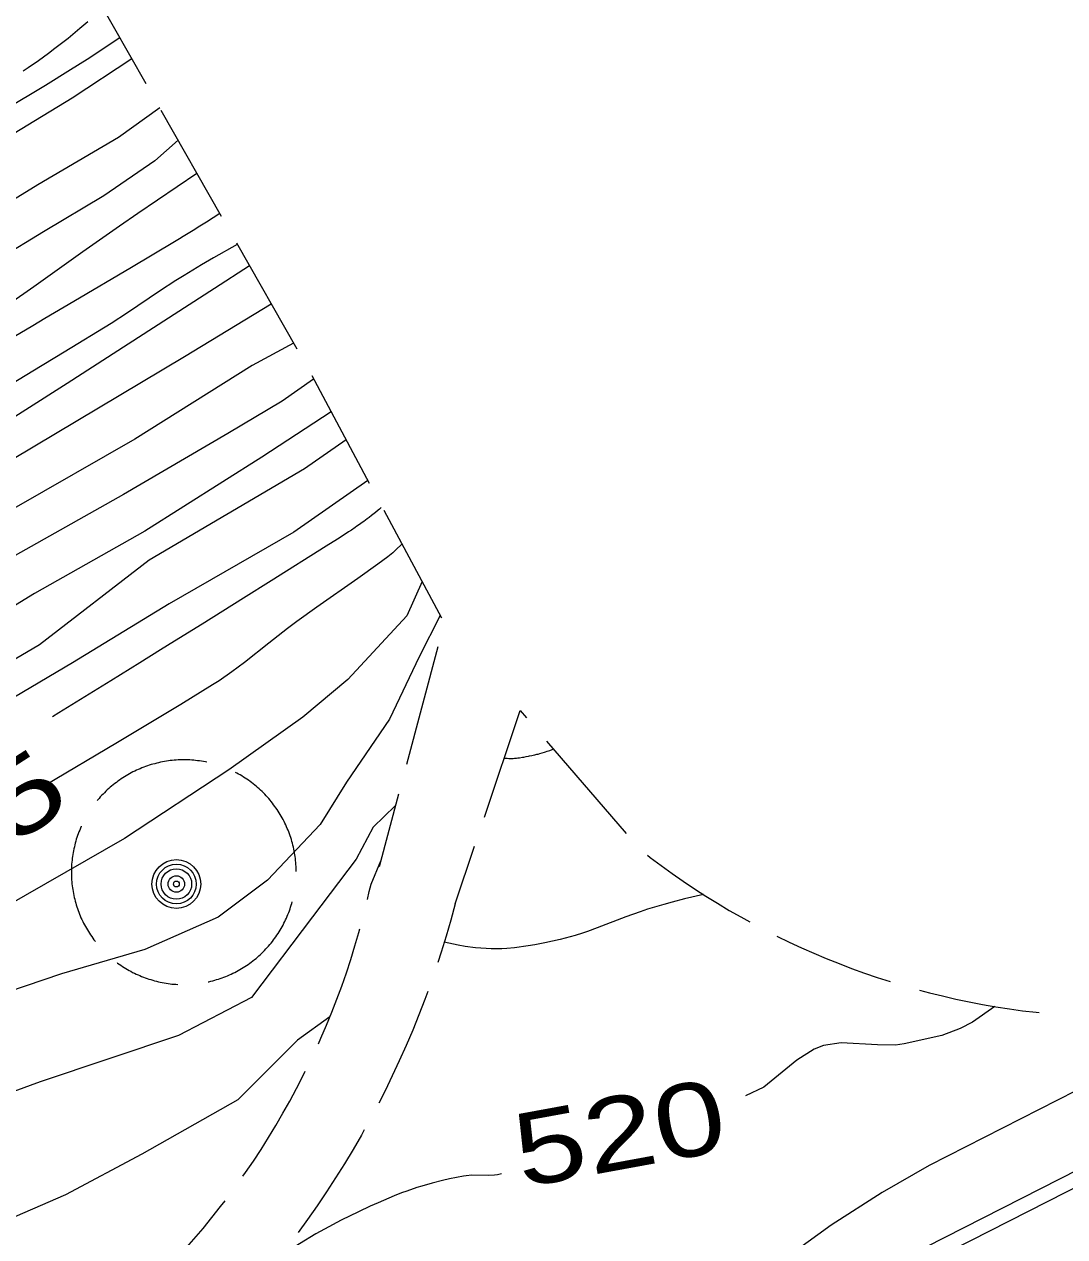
# Model space of a CAD drawing. Extents: x 2361284 to 2366480, y 6976556 to 6985346.
# Drawn here: x 2364307.7 to 2364375.8, y 6978882 to 6978961.5 of the extents above; entities that cross this region are included whole.
import ezdxf
from ezdxf.enums import TextEntityAlignment as Align

# ---------------------------------------------------------------- set-up
doc = ezdxf.new("R2010")
doc.units = 0
doc.header["$LTSCALE"] = 1.9
for name, color, linetype, lineweight in [('12', 7, 'Continuous', 13), ('13', 7, 'Continuous', 13), ('24', 7, 'Continuous', 13), ('25', 7, 'Continuous', 13), ('3', 7, 'Continuous', 13), ('4', 7, 'Continuous', 13), ('6', 7, 'Continuous', 13)]:
    doc.layers.add(name, color=color, linetype=linetype, lineweight=lineweight)

msp = doc.modelspace()

# ---------------------------------------------------------------- linework, layer by layer
at = {"layer": '12'}
for points in [[(2364313.918, 6978960.587), (2364311.774, 6978959.17), (2364310.694, 6978958.476), (2364309.057, 6978957.459), (2364306.384, 6978955.853), (2364305.042, 6978955.059), (2364303.021, 6978953.882), (2364294.02, 6978948.696), (2364288.58, 6978945.564), (2364287.657, 6978945.042), (2364285.795, 6978944.028), (2364283.917, 6978943.04), (2364281.406, 6978941.739), (2364280.152, 6978941.085), (2364272.767, 6978937.243), (2364272.057, 6978936.862), (2364270.648, 6978936.079), (2364267.845, 6978934.487), (2364266.431, 6978933.713)], [(2364320.468, 6978949.068), (2364319.595, 6978948.512), (2364319.158, 6978948.235), (2364318.719, 6978947.96), (2364318.5, 6978947.824), (2364318.059, 6978947.553), (2364317.838, 6978947.419), (2364317.505, 6978947.219), (2364314.675, 6978945.538), (2364310.9, 6978943.299), (2364309.013, 6978942.179), (2364308.221, 6978941.708), (2364306.637, 6978940.764), (2364304.526, 6978939.506), (2364303.47, 6978938.878), (2364302.412, 6978938.252), (2364301.883, 6978937.94), (2364301.746, 6978937.861), (2364301.654, 6978937.81), (2364301.469, 6978937.709), (2364301.282, 6978937.611), (2364300.908, 6978937.416), (2364300.722, 6978937.318), (2364300.629, 6978937.268)], [(2364326.611, 6978938.216), (2364324.545, 6978936.776), (2364320.995, 6978934.652), (2364314.153, 6978930.657), (2364305.499, 6978925.774), (2364295.295, 6978919.817), (2364285.121, 6978913.85), (2364278.029, 6978909.862), (2364269.164, 6978904.928), (2364259.758, 6978899.318), (2364253.637, 6978896.12)], [(2364332.404, 6978927.41), (2364332.007, 6978927.026), (2364331.802, 6978926.842), (2364331.482, 6978926.581), (2364330.827, 6978926.096), (2364329.502, 6978925.148), (2364326.834, 6978923.283), (2364325.512, 6978922.334), (2364324.898, 6978921.873), (2364323.689, 6978920.922), (2364322.081, 6978919.649), (2364321.261, 6978919.035), (2364320.421, 6978918.45), (2364319.991, 6978918.172), (2364317.923, 6978916.897), (2364313.757, 6978914.402), (2364308.994, 6978911.557)], [(2364371.245, 6978897.098), (2364369.778, 6978896.069), (2364368.969, 6978895.656), (2364367.766, 6978895.208), (2364365.307, 6978894.651), (2364364.728, 6978894.579), (2364363.549, 6978894.588), (2364361.18, 6978894.717), (2364360.028, 6978894.551), (2364359.401, 6978894.313), (2364358.265, 6978893.576), (2364356.118, 6978891.827), (2364354.909, 6978891.251)], [(2364338.927, 6978886.13), (2364338.657, 6978886.07), (2364338.474, 6978886.046), (2364338.104, 6978886.027), (2364336.981, 6978886.041), (2364336.611, 6978886.015), (2364336.428, 6978885.986), (2364335.516, 6978885.8), (2364335.063, 6978885.697), (2364334.386, 6978885.528), (2364333.714, 6978885.339), (2364333.38, 6978885.236), (2364332.715, 6978885.012), (2364332.384, 6978884.89), (2364331.89, 6978884.693), (2364330.843, 6978884.244), (2364330.327, 6978884.013), (2364329.561, 6978883.657), (2364328.429, 6978883.098), (2364327.318, 6978882.507), (2364326.77, 6978882.198), (2364325.687, 6978881.55), (2364325.152, 6978881.211), (2364324.358, 6978880.681)]]:
    msp.add_lwpolyline(points, dxfattribs=at)
at = {"layer": '13'}
for points in [[(2364311.814, 6978961.634), (2364311.31, 6978961.188), (2364310.528, 6978960.545), (2364309.671, 6978959.882), (2364309.238, 6978959.558), (2364308.582, 6978959.083), (2364307.916, 6978958.624), (2364307.579, 6978958.402)], [(2364314.701, 6978959.203), (2364310.805, 6978956.626), (2364301.568, 6978951.008), (2364293.845, 6978946.104), (2364290.559, 6978944.303), (2364286.069, 6978942.094), (2364283.864, 6978940.92), (2364280.716, 6978938.984), (2364276.567, 6978936.318), (2364274.427, 6978935.099), (2364269.182, 6978932.479)], [(2364316.532, 6978955.99), (2364313.83, 6978954.045), (2364308.549, 6978950.944), (2364301.013, 6978946.312), (2364290.002, 6978940.078), (2364279.118, 6978934.144), (2364270.162, 6978929.378), (2364260.616, 6978924.797), (2364250.162, 6978919.738), (2364238.779, 6978913.839), (2364222.473, 6978904.794), (2364208.884, 6978898.294), (2364198.941, 6978893.349), (2364192.8, 6978890.28), (2364187.441, 6978887.919), (2364182.588, 6978886.174)], [(2364317.732, 6978953.872), (2364316.215, 6978952.527), (2364312.866, 6978950.235), (2364308.919, 6978947.858), (2364303.172, 6978944.383), (2364296.111, 6978940.047), (2364293.196, 6978938.609), (2364289.982, 6978936.897), (2364285.307, 6978934.273), (2364277.615, 6978930.199), (2364274.488, 6978928.779), (2364265.759, 6978924.536), (2364257, 6978920.083), (2364251.317, 6978917.199), (2364241.61, 6978912.586), (2364232.239, 6978907.367), (2364220.519, 6978902.065), (2364210.333, 6978897.408), (2364201.691, 6978893.355), (2364192.004, 6978887.792), (2364184.189, 6978883.929)], [(2364318.973, 6978951.693), (2364315.107, 6978949.077), (2364313.895, 6978948.243), (2364311.49, 6978946.548), (2364308.294, 6978944.271), (2364306.687, 6978943.145), (2364305.067, 6978942.038), (2364304.249, 6978941.494), (2364303.9, 6978941.269), (2364303.19, 6978940.839), (2364302.469, 6978940.428), (2364301.006, 6978939.643)], [(2364321.617, 6978947.048), (2364320.051, 6978946.169), (2364319.276, 6978945.716), (2364318.126, 6978945.015), (2364317.59, 6978944.673), (2364316.529, 6978943.971), (2364314.418, 6978942.553), (2364313.346, 6978941.87), (2364310.274, 6978939.986), (2364308.222, 6978938.736), (2364304.109, 6978936.251), (2364303.085, 6978935.642)], [(2364322.411, 6978945.636), (2364320.125, 6978944.144), (2364310.463, 6978937.922), (2364299.847, 6978931.181), (2364286.905, 6978923.987), (2364274.065, 6978916.445), (2364261.964, 6978910.31), (2364246.754, 6978902.725), (2364228.872, 6978893.373), (2364216.324, 6978887.844), (2364203.202, 6978880.669), (2364189.183, 6978874.156), (2364178.057, 6978868.389)], [(2364323.844, 6978943.13), (2364318.147, 6978939.686), (2364306.88, 6978932.948), (2364295.455, 6978926.009), (2364285.901, 6978920.148), (2364275.256, 6978914.176), (2364260.532, 6978906.236), (2364244.509, 6978897.973), (2364228.357, 6978890.738), (2364215.431, 6978883.976), (2364202.153, 6978876.299), (2364186.212, 6978868.926), (2364172.253, 6978862.503)], [(2364325.299, 6978940.564), (2364322.583, 6978939.118), (2364314.908, 6978934.274), (2364306.971, 6978929.738), (2364298.615, 6978924.909), (2364288.728, 6978919.404), (2364276.576, 6978912.129), (2364273.468, 6978910.461), (2364267.173, 6978907.279), (2364262.694, 6978905.157), (2364256.711, 6978902.354), (2364253.782, 6978900.831)], [(2364327.762, 6978936.066), (2364323.23, 6978933.103), (2364315.565, 6978928.26), (2364308.324, 6978924.161), (2364302.02, 6978920.301), (2364294.83, 6978916.112), (2364284.978, 6978909.978), (2364276.55, 6978905.398), (2364266.147, 6978899.499), (2364262.975, 6978897.89), (2364258.686, 6978895.86), (2364256.561, 6978894.807)], [(2364328.739, 6978934.245), (2364326.017, 6978932.33), (2364315.843, 6978926.363), (2364308.656, 6978920.804), (2364301.884, 6978916.819), (2364294.629, 6978912.04), (2364283.168, 6978905.721), (2364273.673, 6978900.83), (2364259.772, 6978893.627), (2364245.846, 6978886.685), (2364235.63, 6978882.178), (2364223.418, 6978875.931), (2364208.701, 6978868.14), (2364196.682, 6978861.656), (2364185.969, 6978857.625), (2364177.208, 6978853.631)], [(2364330.174, 6978931.579), (2364325.317, 6978928.183), (2364317.151, 6978923.485), (2364310.817, 6978919.634), (2364299.4, 6978912.866), (2364289.25, 6978906.569), (2364276.268, 6978899.285), (2364261.484, 6978891.283), (2364243.048, 6978882.278), (2364226.448, 6978874.88), (2364207.744, 6978865.701), (2364193.385, 6978858.155), (2364173.139, 6978849.311)], [(2364331.051, 6978929.797), (2364330.927, 6978929.69), (2364330.843, 6978929.62), (2364330.675, 6978929.481), (2364330.59, 6978929.412), (2364330.418, 6978929.277), (2364330.245, 6978929.145), (2364330.129, 6978929.057), (2364329.895, 6978928.886), (2364329.807, 6978928.822), (2364329.629, 6978928.696), (2364329.45, 6978928.572), (2364329.33, 6978928.49), (2364329.088, 6978928.328), (2364328.906, 6978928.208), (2364328.541, 6978927.971), (2364328.173, 6978927.737), (2364327.435, 6978927.273), (2364323.824, 6978925.002), (2364322.018, 6978923.867), (2364319.308, 6978922.167), (2364317.5, 6978921.036), (2364316.595, 6978920.471), (2364315.237, 6978919.626), (2364314.601, 6978919.231), (2364313.328, 6978918.445), (2364311.63, 6978917.397), (2364310.782, 6978916.872), (2364309.934, 6978916.346), (2364309.511, 6978916.082)], [(2364333.718, 6978924.952), (2364332.719, 6978922.713), (2364328.868, 6978918.536), (2364325.902, 6978916.058), (2364321.064, 6978912.612), (2364314.217, 6978908.106), (2364305.186, 6978902.93), (2364289.118, 6978895.237), (2364266.502, 6978884.211), (2364245.631, 6978872.543), (2364232.916, 6978865.69), (2364217.944, 6978858.399), (2364197.912, 6978849.017), (2364174.548, 6978838.904), (2364149.077, 6978827.261), (2364118.91, 6978813.034), (2364092.542, 6978799.043), (2364063.56, 6978784.396), (2364043.9, 6978774.808), (2364026.318, 6978766.382), (2364019.32, 6978763.015), (2364007.167, 6978756.928), (2364005.706, 6978756.044)], [(2364334.909, 6978922.734), (2364333.535, 6978920.01), (2364331.593, 6978915.931), (2364328.763, 6978911.795), (2364327.049, 6978909.028), (2364323.603, 6978905.385), (2364320.366, 6978902.954), (2364315.556, 6978900.839), (2364310.091, 6978899.237), (2364300.761, 6978896.068), (2364289.102, 6978890.676), (2364267.935, 6978880.645), (2364242.203, 6978867.089), (2364227.709, 6978858.971), (2364208.292, 6978849.085), (2364188.54, 6978839.667), (2364172.369, 6978831.383)], [(2364339.108, 6978913.383), (2364339.238, 6978913.373), (2364339.303, 6978913.369), (2364339.401, 6978913.365), (2364339.499, 6978913.363), (2364339.548, 6978913.363), (2364339.646, 6978913.364), (2364339.695, 6978913.366), (2364339.769, 6978913.37), (2364339.867, 6978913.376), (2364339.915, 6978913.381), (2364339.989, 6978913.389), (2364340.098, 6978913.403), (2364340.298, 6978913.434), (2364340.397, 6978913.451), (2364340.546, 6978913.477), (2364340.695, 6978913.505), (2364340.769, 6978913.52), (2364340.917, 6978913.551), (2364340.991, 6978913.567), (2364341.101, 6978913.593), (2364341.248, 6978913.629), (2364341.321, 6978913.648), (2364341.43, 6978913.678), (2364341.594, 6978913.725), (2364341.739, 6978913.77), (2364341.811, 6978913.793), (2364341.919, 6978913.83), (2364342.081, 6978913.889), (2364342.242, 6978913.951), (2364342.322, 6978913.984)], [(2364331.967, 6978910.255), (2364330.521, 6978908.851), (2364329.4, 6978906.751), (2364326.536, 6978902.983), (2364322.537, 6978897.695), (2364317.76, 6978895.199), (2364308.698, 6978892.172), (2364298.323, 6978888.363), (2364287.115, 6978882.957), (2364273.099, 6978876.074), (2364260.97, 6978869.627), (2364253.351, 6978866.215), (2364238.413, 6978858.772), (2364224.594, 6978851.072), (2364210.507, 6978844.356), (2364196.393, 6978837.392), (2364175.496, 6978828.524)], [(2364352.154, 6978904.437), (2364350.92, 6978904.151), (2364350.104, 6978903.939), (2364349.563, 6978903.789), (2364348.484, 6978903.472), (2364348.005, 6978903.318), (2364347.061, 6978902.976), (2364345.184, 6978902.248), (2364344.549, 6978902.019), (2364344.228, 6978901.911), (2364343.741, 6978901.759), (2364343.415, 6978901.664), (2364342.76, 6978901.49), (2364341.773, 6978901.267), (2364341.112, 6978901.142), (2364340.67, 6978901.07), (2364339.786, 6978900.949), (2364339.278, 6978900.902), (2364338.937, 6978900.885), (2364338.253, 6978900.881), (2364337.91, 6978900.895), (2364337.223, 6978900.95), (2364336.536, 6978901.041), (2364336.079, 6978901.119), (2364335.776, 6978901.179), (2364335.172, 6978901.315)], [(2364327.689, 6978896.424), (2364325.563, 6978894.894), (2364321.65, 6978890.995), (2364315.364, 6978887.416), (2364310.359, 6978884.768), (2364301.196, 6978880.791), (2364288.663, 6978875.802), (2364279.434, 6978872.464), (2364262.589, 6978865.572), (2364246.385, 6978856.389), (2364230.353, 6978848.095), (2364216.065, 6978841.509), (2364197.646, 6978832.833), (2364179.789, 6978824.093), (2364157.795, 6978813.724), (2364135.375, 6978803.079), (2364112.416, 6978792.381), (2364095.188, 6978785.777), (2364076.216, 6978777.435), (2364052.051, 6978767.296), (2364031.409, 6978757.949), (2364020.369, 6978752.603), (2364007.838, 6978746.374), (2363983.332, 6978733.19)], [(2364384.218, 6978896.741), (2364382.437, 6978895.164), (2364381.48, 6978894.455), (2364380.263, 6978893.655), (2364377.752, 6978892.199), (2364366.954, 6978886.677), (2364363.87, 6978884.917), (2364360.53, 6978882.775), (2364356.637, 6978879.948), (2364352.777, 6978877.771), (2364346.887, 6978874.695), (2364345.485, 6978873.851), (2364342.802, 6978871.99), (2364340.257, 6978869.935), (2364338.625, 6978868.481), (2364335.474, 6978865.435)]]:
    msp.add_lwpolyline(points, dxfattribs=at)
at = {"layer": '24'}
for p, q in [((2364311.67, 6978964.536), (2364315.627, 6978957.582)), ((2364316.613, 6978955.841), (2364320.569, 6978948.888)), ((2364321.556, 6978947.148), (2364325.512, 6978940.196)), ((2364326.489, 6978938.455), (2364330.266, 6978931.4)), ((2364331.213, 6978929.639), (2364334.99, 6978922.584)), ((2364334.748, 6978920.682), (2364332.692, 6978912.952)), ((2364341.877, 6978914.5), (2364347.096, 6978908.439)), ((2364332.18, 6978911.017), (2364330.905, 6978906.255)), ((2364335.879, 6978903.822), (2364337.163, 6978907.614))]:
    msp.add_line(p, q, dxfattribs=at)
for points in [[(2364337.805, 6978909.511), (2364340.158, 6978916.493), (2364340.573, 6978916.017)], [(2364348.49, 6978907.012), (2364348.671, 6978906.874), (2364349.376, 6978906.35), (2364350.101, 6978905.827), (2364350.836, 6978905.314), (2364351.57, 6978904.821), (2364352.314, 6978904.338), (2364353.069, 6978903.865), (2364353.833, 6978903.403), (2364354.608, 6978902.97), (2364355.191, 6978902.656)], [(2364356.96, 6978901.712), (2364357.763, 6978901.33), (2364358.577, 6978900.958), (2364359.39, 6978900.595), (2364360.204, 6978900.253), (2364361.037, 6978899.921), (2364361.86, 6978899.599), (2364362.703, 6978899.297), (2364363.546, 6978899.005), (2364364.378, 6978898.733)], [(2364366.305, 6978898.181), (2364366.956, 6978898.007), (2364367.818, 6978897.795), (2364368.69, 6978897.594), (2364369.562, 6978897.412), (2364370.434, 6978897.24), (2364371.315, 6978897.089), (2364372.197, 6978896.957), (2364373.068, 6978896.825), (2364373.959, 6978896.724), (2364374.159, 6978896.706)]]:
    msp.add_lwpolyline(points, dxfattribs=at)
at = {"layer": '25'}
for points in [[(2364319.63, 6978913.108), (2364319.529, 6978913.127), (2364319.399, 6978913.156), (2364319.269, 6978913.174), (2364319.149, 6978913.193), (2364319.019, 6978913.212), (2364318.888, 6978913.231), (2364318.758, 6978913.24), (2364318.638, 6978913.249), (2364318.508, 6978913.257), (2364318.378, 6978913.266), (2364318.248, 6978913.265), (2364318.118, 6978913.264), (2364317.988, 6978913.262), (2364317.868, 6978913.261), (2364317.738, 6978913.26), (2364317.608, 6978913.249), (2364317.478, 6978913.237), (2364317.348, 6978913.226), (2364317.218, 6978913.215), (2364317.099, 6978913.194), (2364316.969, 6978913.183), (2364316.839, 6978913.161), (2364316.719, 6978913.13), (2364316.589, 6978913.109), (2364316.46, 6978913.078), (2364316.34, 6978913.047), (2364316.21, 6978913.015), (2364316.091, 6978912.984), (2364315.971, 6978912.953), (2364315.841, 6978912.912), (2364315.722, 6978912.871), (2364315.602, 6978912.83), (2364315.483, 6978912.778), (2364315.363, 6978912.737), (2364315.243, 6978912.686), (2364315.124, 6978912.635), (2364315.004, 6978912.584), (2364314.895, 6978912.523), (2364314.775, 6978912.472), (2364314.666, 6978912.411), (2364314.547, 6978912.35), (2364314.437, 6978912.289), (2364314.328, 6978912.217), (2364314.218, 6978912.156), (2364314.109, 6978912.085), (2364314, 6978912.014), (2364313.89, 6978911.943), (2364313.791, 6978911.862), (2364313.692, 6978911.791), (2364313.583, 6978911.71), (2364313.483, 6978911.629), (2364313.384, 6978911.548), (2364313.285, 6978911.468), (2364313.196, 6978911.387), (2364313.097, 6978911.296), (2364313.007, 6978911.205), (2364312.908, 6978911.114), (2364312.819, 6978911.023), (2364312.73, 6978910.932), (2364312.641, 6978910.841), (2364312.562, 6978910.741), (2364312.473, 6978910.64), (2364312.443, 6978910.609)], [(2364325.478, 6978905.943), (2364325.477, 6978906.023), (2364325.476, 6978906.153), (2364325.465, 6978906.283), (2364325.454, 6978906.403), (2364325.452, 6978906.533), (2364325.431, 6978906.663), (2364325.42, 6978906.793), (2364325.409, 6978906.923), (2364325.388, 6978907.042), (2364325.366, 6978907.172), (2364325.345, 6978907.302), (2364325.314, 6978907.422), (2364325.293, 6978907.552), (2364325.262, 6978907.671), (2364325.23, 6978907.801), (2364325.189, 6978907.921), (2364325.158, 6978908.05), (2364325.117, 6978908.17), (2364325.076, 6978908.289), (2364325.035, 6978908.409), (2364324.993, 6978908.539), (2364324.942, 6978908.648), (2364324.891, 6978908.768), (2364324.84, 6978908.887), (2364324.789, 6978909.007), (2364324.738, 6978909.126), (2364324.677, 6978909.236), (2364324.616, 6978909.355), (2364324.554, 6978909.465), (2364324.493, 6978909.574), (2364324.432, 6978909.683), (2364324.361, 6978909.803), (2364324.29, 6978909.902), (2364324.219, 6978910.011), (2364324.148, 6978910.121), (2364324.077, 6978910.22), (2364323.996, 6978910.329), (2364323.915, 6978910.429), (2364323.844, 6978910.528), (2364323.763, 6978910.627), (2364323.672, 6978910.726), (2364323.591, 6978910.825), (2364323.501, 6978910.915), (2364323.42, 6978911.014), (2364323.33, 6978911.103), (2364323.239, 6978911.192), (2364323.138, 6978911.281), (2364323.047, 6978911.37), (2364322.946, 6978911.459), (2364322.856, 6978911.539), (2364322.755, 6978911.618), (2364322.654, 6978911.697), (2364322.553, 6978911.776), (2364322.453, 6978911.855), (2364322.342, 6978911.934), (2364322.241, 6978912.003), (2364322.131, 6978912.072), (2364322.02, 6978912.141), (2364321.909, 6978912.21), (2364321.798, 6978912.279), (2364321.687, 6978912.337), (2364321.576, 6978912.396), (2364321.506, 6978912.436)], [(2364311.389, 6978908.919), (2364311.389, 6978908.909), (2364311.34, 6978908.789), (2364311.291, 6978908.668), (2364311.243, 6978908.548), (2364311.194, 6978908.428), (2364311.155, 6978908.307), (2364311.106, 6978908.187), (2364311.067, 6978908.066), (2364311.038, 6978907.946), (2364311, 6978907.816), (2364310.971, 6978907.695), (2364310.942, 6978907.565), (2364310.913, 6978907.445), (2364310.884, 6978907.315), (2364310.865, 6978907.194), (2364310.837, 6978907.064), (2364310.818, 6978906.934), (2364310.799, 6978906.814), (2364310.79, 6978906.684), (2364310.782, 6978906.553), (2364310.763, 6978906.423), (2364310.754, 6978906.303), (2364310.755, 6978906.173), (2364310.746, 6978906.043), (2364310.748, 6978905.913), (2364310.749, 6978905.783), (2364310.75, 6978905.653), (2364310.761, 6978905.523), (2364310.762, 6978905.403), (2364310.774, 6978905.273), (2364310.785, 6978905.143), (2364310.806, 6978905.014), (2364310.817, 6978904.884), (2364310.839, 6978904.764), (2364310.86, 6978904.634), (2364310.881, 6978904.504), (2364310.902, 6978904.385), (2364310.933, 6978904.255), (2364310.965, 6978904.135), (2364310.996, 6978904.005), (2364311.027, 6978903.886), (2364311.068, 6978903.756), (2364311.109, 6978903.636), (2364311.15, 6978903.517), (2364311.192, 6978903.397), (2364311.233, 6978903.278), (2364311.284, 6978903.158), (2364311.325, 6978903.039), (2364311.376, 6978902.919), (2364311.437, 6978902.8), (2364311.488, 6978902.68), (2364311.549, 6978902.571), (2364311.601, 6978902.451), (2364311.662, 6978902.342), (2364311.733, 6978902.232), (2364311.794, 6978902.123), (2364311.865, 6978902.014), (2364311.926, 6978901.904), (2364311.997, 6978901.795), (2364312.078, 6978901.686), (2364312.149, 6978901.586), (2364312.22, 6978901.477), (2364312.301, 6978901.378), (2364312.311, 6978901.368)], [(2364319.716, 6978898.718), (2364319.756, 6978898.728), (2364319.886, 6978898.76), (2364320.006, 6978898.791), (2364320.135, 6978898.822), (2364320.255, 6978898.863), (2364320.375, 6978898.894), (2364320.504, 6978898.936), (2364320.624, 6978898.977), (2364320.744, 6978899.028), (2364320.863, 6978899.069), (2364320.983, 6978899.12), (2364321.102, 6978899.171), (2364321.212, 6978899.222), (2364321.331, 6978899.283), (2364321.451, 6978899.335), (2364321.56, 6978899.396), (2364321.669, 6978899.457), (2364321.789, 6978899.518), (2364321.899, 6978899.589), (2364322.009, 6978899.65), (2364322.118, 6978899.721), (2364322.227, 6978899.792), (2364322.327, 6978899.863), (2364322.436, 6978899.944), (2364322.535, 6978900.015), (2364322.634, 6978900.096), (2364322.744, 6978900.177), (2364322.843, 6978900.258), (2364322.932, 6978900.339), (2364323.031, 6978900.43), (2364323.131, 6978900.511), (2364323.22, 6978900.601), (2364323.309, 6978900.692), (2364323.398, 6978900.783), (2364323.486, 6978900.874), (2364323.575, 6978900.965), (2364323.664, 6978901.066), (2364323.743, 6978901.166), (2364323.832, 6978901.257), (2364323.912, 6978901.358), (2364323.99, 6978901.469), (2364324.06, 6978901.57), (2364324.139, 6978901.67), (2364324.208, 6978901.781), (2364324.287, 6978901.882), (2364324.356, 6978901.992), (2364324.414, 6978902.103), (2364324.483, 6978902.214), (2364324.552, 6978902.324), (2364324.611, 6978902.435), (2364324.67, 6978902.555), (2364324.729, 6978902.666), (2364324.778, 6978902.786), (2364324.837, 6978902.897), (2364324.886, 6978903.017), (2364324.935, 6978903.138), (2364324.984, 6978903.258), (2364325.032, 6978903.379), (2364325.071, 6978903.499), (2364325.11, 6978903.62), (2364325.149, 6978903.74), (2364325.188, 6978903.86), (2364325.217, 6978903.971)], [(2364313.744, 6978899.981), (2364313.774, 6978899.952), (2364313.875, 6978899.873), (2364313.986, 6978899.804)], [(2364313.986, 6978899.804), (2364314.097, 6978899.735), (2364314.197, 6978899.666), (2364314.308, 6978899.597), (2364314.418, 6978899.528), (2364314.529, 6978899.469), (2364314.65, 6978899.41), (2364314.76, 6978899.341), (2364314.871, 6978899.292), (2364314.991, 6978899.233), (2364315.112, 6978899.184), (2364315.222, 6978899.125), (2364315.343, 6978899.077), (2364315.463, 6978899.028), (2364315.584, 6978898.989), (2364315.704, 6978898.94), (2364315.825, 6978898.901), (2364315.945, 6978898.862), (2364316.075, 6978898.823), (2364316.196, 6978898.795), (2364316.316, 6978898.756), (2364316.446, 6978898.727), (2364316.566, 6978898.698), (2364316.697, 6978898.679), (2364316.827, 6978898.651), (2364316.947, 6978898.632), (2364317.077, 6978898.613), (2364317.207, 6978898.594), (2364317.328, 6978898.575), (2364317.458, 6978898.567), (2364317.588, 6978898.558), (2364317.718, 6978898.549), (2364317.728, 6978898.549)]]:
    msp.add_lwpolyline(points, dxfattribs=at)
at = {"layer": '3'}
for points in [[(2364281.62, 6978838.05), (2364281.605, 6978838.043), (2364415.56, 6978906.188)], [(2364282.039, 6978837.186), (2364282.04, 6978837.187), (2364415.996, 6978905.332)]]:
    msp.add_lwpolyline(points, dxfattribs=at)
at = {"layer": '4'}
for radius in [1.6, 1.3, 1, 0.539, 0.192]:
    msp.add_circle((2364317.625, 6978905.129), radius, dxfattribs=at)
at = {"layer": '6'}
for points in [[(2364330.146, 6978904.117), (2364330.261, 6978904.629), (2364330.376, 6978905.13), (2364331.012, 6978906.646)], [(2364335.879, 6978903.822), (2364335.599, 6978902.759), (2364335.299, 6978901.716), (2364334.969, 6978900.673), (2364334.755, 6978899.981)], [(2364326.925, 6978894.666), (2364327.092, 6978895.038), (2364327.464, 6978895.872), (2364327.806, 6978896.735), (2364328.138, 6978897.588), (2364328.459, 6978898.441), (2364328.771, 6978899.314), (2364329.053, 6978900.187), (2364329.325, 6978901.07), (2364329.586, 6978901.952), (2364329.644, 6978902.183)], [(2364334.093, 6978898.095), (2364333.908, 6978897.573), (2364333.518, 6978896.549), (2364333.107, 6978895.545), (2364332.677, 6978894.541), (2364332.226, 6978893.536), (2364331.766, 6978892.551), (2364331.295, 6978891.567), (2364330.882, 6978890.773)], [(2364321.989, 6978885.989), (2364322.156, 6978886.221), (2364322.669, 6978886.976), (2364323.182, 6978887.74), (2364323.664, 6978888.524), (2364324.146, 6978889.309), (2364324.609, 6978890.103), (2364325.061, 6978890.908), (2364325.493, 6978891.722), (2364325.915, 6978892.536), (2364326.072, 6978892.857)], [(2364329.929, 6978889.014), (2364329.742, 6978888.672), (2364329.201, 6978887.727), (2364328.64, 6978886.792), (2364328.059, 6978885.867), (2364327.458, 6978884.951), (2364326.846, 6978884.045), (2364326.225, 6978883.149), (2364325.603, 6978882.293)], [(2364315.499, 6978878.397), (2364315.618, 6978878.508), (2364316.282, 6978879.155), (2364316.916, 6978879.811), (2364317.55, 6978880.487), (2364318.163, 6978881.163), (2364318.777, 6978881.858), (2364319.37, 6978882.564), (2364319.953, 6978883.27), (2364320.526, 6978883.995), (2364320.813, 6978884.368)]]:
    msp.add_lwpolyline(points, dxfattribs=at)

# ---------------------------------------------------------------- texts
at = {"layer": '12'}
for s, rotation, width, p in [(' 525 ', 32.685, 1.4, (2364304.658, 6978906.226)), (' 520 ', 10.393, 1.3, (2364347.093, 6978886.474))]:
    msp.add_text(s, height=4.8, rotation=rotation, dxfattribs=dict(at, width=width)).set_placement(p, align=Align.CENTER)

doc.saveas('drawing.dxf')
